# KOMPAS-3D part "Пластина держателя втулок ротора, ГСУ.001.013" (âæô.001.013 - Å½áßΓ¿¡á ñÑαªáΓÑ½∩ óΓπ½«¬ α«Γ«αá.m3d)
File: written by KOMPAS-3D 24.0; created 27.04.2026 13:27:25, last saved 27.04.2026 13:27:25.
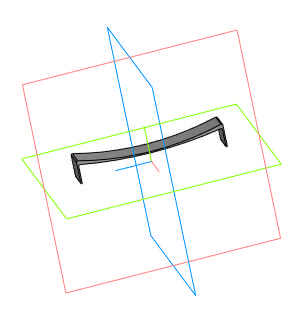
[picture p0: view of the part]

Document properties: Автор: User7; Полное имя файла: C:\Users\User7\Desktop\олимп\ГСУ.001.013 - Пластина держателя втулок ротора.m3d

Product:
- Part/product: Пластина держателя втулок ротора  | designation ГСУ.001.013
    Масса: 0.000957

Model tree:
1. Эскиз:1
2. Элемент выдавливания:1
     Расстояние 1 = 6
3. Скругление:1  (with: Ребро.Элемент выдавливания:1)
     Радиус = 0.3
4. Зеркальный массив:1
5. Экземпляр ( 1 )
6. Экземпляр ( 2 )  (with: Элемент выдавливания:1, Скругление:1)

Expressions: 34.1/2
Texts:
  ГСУ.001.013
